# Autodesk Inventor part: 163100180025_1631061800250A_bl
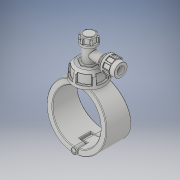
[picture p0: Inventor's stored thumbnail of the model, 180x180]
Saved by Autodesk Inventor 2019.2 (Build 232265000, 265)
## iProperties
Created: 2022-02
Part Number: 163100180025_1631061800250A_bl
Material: Generic
Description: Plassadle Tapper 160x25
Document SubType Name: Modeling
Designer: comp2
Density: 1 g/cm^3
Appearance: Default
Author: comp2
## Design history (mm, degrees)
derived "16310.ipt"
feature "Solid1::16310.ipt" dims "ScaleForDerivedMember" = 10
feature "Solid2::16310.ipt" dims "ScaleForDerivedMember" = 10
feature "Solid3::16310.ipt" dims "ScaleForDerivedMember" = 10
feature "Solid4::16310.ipt" dims "ScaleForDerivedMember" = 10
tag "TaggingFeature1"
body "Solid1"
body "Solid2"
body "Solid3"
body "Solid4"
other parameters: "d2" = 198 [user parameter], "d5" = 325 [user parameter], "d7" = 188.1 [user parameter], "d8" = 85 deg [user parameter], "d9" = 45 deg [user parameter], "d10" = 102 [user parameter], "d11" = 49 [user parameter], "d12" = 34.3 [user parameter], "d13" = 35.7 [user parameter], "d14" = 55.08 [user parameter], "d15" = 2.45 [user parameter], "d16" = 2 [user parameter], "d17" = 2 [user parameter], "d18" = 29.4 [user parameter], "d19" = 7.35 [user parameter], "d20" = 1 [user parameter], "d21" = 30.6 [user parameter], "d22" = 1 [user parameter], "d23" = 14.7 [user parameter], "d24" = 106 [user parameter], "d27" = 144 [user parameter], "d29" = 54 [user parameter], "d31" = 43.2 [user parameter], "d32" = 42.4 [user parameter], "d33" = 14.84 [user parameter], "d34" = 93 deg [user parameter], "d35" = 2 [user parameter], "d36" = 4 [user parameter], "d39" = 45 deg [user parameter], "d40" = 4 [user parameter], "d41" = 5 [user parameter], "d42" = 3.8 [user parameter], "d46" = 51 [user parameter], "d47" = 27 [user parameter], "d48" = 49 [user parameter], "d49" = 3.96 [user parameter], "d50" = 106 [user parameter], "d51" = 0 [user parameter], "d52" = 26.6 [user parameter], "d53" = 108.9 [user parameter], "d54" = 37.1 [user parameter], "d55" = 0 [user parameter], "d56" = 21.2 [user parameter], "d57" = 21.2 [user parameter], "d59" = 0 [user parameter], "d60" = 106 [user parameter], "d61" = 0 [user parameter], "d62" = 37.1 [user parameter], "d63" = 0 [user parameter], "d65" = 0 [user parameter], "d67" = 0 [user parameter], "d69" = 0 [user parameter], "d70" = 1 [user parameter], "d71" = 101.76 [user parameter], "d72" = 0 [user parameter], "d73" = 2 [user parameter], "d77" = 25 [user parameter], "d78" = 86.7 [user parameter], "d79" = 5.1 [user parameter], "d80" = 60 deg [user parameter], "d81" = 5.1 [user parameter], "d84" = 0 [user parameter], "d85" = 1 [user parameter], "d87" = 360 deg [user parameter], "d90" = 0 [user parameter], "d91" = 1 [user parameter], "d93" = 60 deg [user parameter], "d94" = 3.06 [user parameter], "d95" = 3.06 [user parameter], "d97" = 0 [user parameter], "d98" = 0.5 [user parameter], "d100" = 360 deg [user parameter], "d102" = 2 [user parameter], "d105" = 0 [user parameter], "d106" = 45 deg [user parameter], "d107" = 2.7 [user parameter], "d108" = 2.7 [user parameter], "d109" = 2.95332 [user parameter], "d110" = -8 [user parameter], "d112" = 0 [user parameter], "d113" = 0.5 [user parameter], "d115" = 360 deg [user parameter], "d117" = 0.5 [user parameter], "d1" = 25 [user parameter], "B" = 198 [user parameter], "L" = 106 [user parameter], "E_" = 54 [user parameter], "E1" = 102 [user parameter], "H1" = 325 [user parameter], "H2" = 144 [user parameter], "H3" = 106 [user parameter], "H_costum" = 49 [user parameter]
